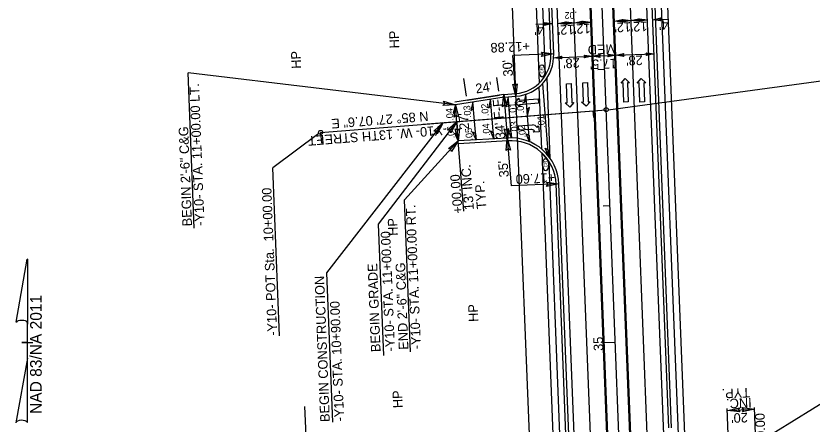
# Model space of a CAD drawing. Extents: x 1627861 to 1629601, y 761281 to 766239.
# Drawn here: x 1627974 to 1628556, y 763914 to 764213 of the extents above; entities that cross this region are included whole.
import ezdxf

# ---------------------------------------------------------------- set-up
doc = ezdxf.new("R2010")
doc.units = 0
for name, color, linetype in [('Cogo Default Point CELL', 7, 'Continuous'), ('Exist Hydro Jurisdictional Stream or Body of Water', 7, 'Continuous'), ('Exist Other Culture Sign Leader', 7, 'Continuous'), ('Exist Property Tie Line Leader', 7, 'Continuous'), ('Exist Property Tie Line Text', 7, 'Continuous'), ('Exist Right of Way Line Leader', 7, 'Continuous'), ('Exist Right of Way Monument Leader', 7, 'Continuous'), ('Exist Right of Way Monument Text', 7, 'Continuous'), ('Exist Utilities Gas Meter CELL', 7, 'Continuous'), ('Exist Utilities Gas Meter Cogo Elevation', 7, 'Continuous'), ('Exist Utilities Gas Meter Cogo Number', 7, 'Continuous'), ('Exist Utilities Gas UG Line', 7, 'Continuous'), ('Exist Utilities Power UG Cable SUE LOS B Cogo Number', 7, 'Continuous'), ('Exist Utilities Power UG Cable SUE LOS B Cogo Point CELL', 7, 'Continuous'), ('Exist Utilities Telephone UG Cable SUE LOS B Cogo Comment', 7, 'Continuous'), ('Exist Utilities Water Fire Hydrant Cogo Elevation', 7, 'Continuous'), ('Exist Utilities Water Fire Hydrant Cogo Number', 7, 'Continuous'), ('Exist Utilities Water Meter Cogo Elevation', 7, 'Continuous'), ('Exist Utilities Water UG Line SUE LOS B Cogo Number', 7, 'Continuous'), ('Exist Utilities Water Valve CELL', 7, 'Continuous'), ('Matchline', 7, 'Continuous'), ('Scratch_Level_0', 7, 'Continuous'), ('Typical Terminator CELL', 7, 'Continuous')]:
    doc.layers.add(name, color=color, linetype=linetype)

msp = doc.modelspace()

# ---------------------------------------------------------------- linework, layer by layer
at = {"layer": 'Exist Hydro Jurisdictional Stream or Body of Water'}
msp.add_line((1628196.62, 764127.74), (1628405.69, 764144.37), dxfattribs=at)
at = {"layer": 'Exist Property Tie Line Text'}
for p, q in [((1628404.53, 764173.83), (1628399.53, 764173.64)), ((1628395.99, 764143.6), (1628396.39, 764138.61)), ((1628296.31, 764135.67), (1628296.7, 764130.68)), ((1628408.47, 764073.91), (1628403.47, 764073.71))]:
    msp.add_line(p, q, dxfattribs=at)
at = {"layer": 'Exist Right of Way Line Leader'}
for p, q in [((1628407.18, 764144.24), (1628629.31, 764174.43)), ((1628195.42, 764126.85), (1628161.61, 764101.87)), ((1628166.47, 763978.73), (1628161.61, 764101.87)), ((1628190.01, 763805.52), (1628185.22, 763927.11))]:
    msp.add_line(p, q, dxfattribs=at)
for centre in [(1628405.69, 764144.37), (1628196.62, 764127.74)]:
    msp.add_circle(centre, 1.5, dxfattribs=at)
at = {"layer": 'Exist Right of Way Monument Leader'}
for p, q in [((1628416.62, 764163.87), (1628419.6, 764167.13)), ((1628419.6, 764167.13), (1628422.91, 764164.09)), ((1628428.42, 764163.86), (1628431.41, 764167.12)), ((1628431.41, 764167.12), (1628434.72, 764164.09)), ((1628376.73, 764163.38), (1628380.03, 764163.49)), ((1628377.23, 764149.39), (1628376.73, 764163.38)), ((1628380.03, 764163.49), (1628380.53, 764149.5)), ((1628388.71, 764164.04), (1628392, 764164.16)), ((1628389.21, 764150.05), (1628388.71, 764164.04)), ((1628392, 764164.16), (1628392.51, 764150.16)), ((1628418.12, 764163.92), (1628416.62, 764163.87)), ((1628418.62, 764149.93), (1628418.12, 764163.92)), ((1628422.91, 764164.09), (1628421.42, 764164.04)), ((1628421.42, 764164.04), (1628421.92, 764150.05)), ((1628429.92, 764163.91), (1628428.42, 764163.86)), ((1628430.42, 764149.92), (1628429.92, 764163.91)), ((1628434.72, 764164.09), (1628433.22, 764164.03)), ((1628433.22, 764164.03), (1628433.72, 764150.04)), ((1628338.98, 764149.31), (1628341.87, 764152.75)), ((1628342.37, 764146.46), (1628338.98, 764149.31)), ((1628341.87, 764152.75), (1628341.99, 764151.25)), ((1628341.99, 764151.25), (1628355.95, 764152.35)), ((1628356.2, 764149.06), (1628342.25, 764147.96)), ((1628342.25, 764147.96), (1628342.37, 764146.46)), ((1628355.95, 764152.35), (1628356.2, 764149.06)), ((1628375.73, 764149.33), (1628377.23, 764149.39)), ((1628379.04, 764146.3), (1628375.73, 764149.33)), ((1628382.03, 764149.56), (1628379.04, 764146.3)), ((1628380.53, 764149.5), (1628382.03, 764149.56)), ((1628387.71, 764149.99), (1628389.21, 764150.05)), ((1628391.02, 764146.96), (1628387.71, 764149.99)), ((1628394.01, 764150.22), (1628391.02, 764146.96)), ((1628392.51, 764150.16), (1628394.01, 764150.22)), ((1628421.92, 764150.05), (1628418.62, 764149.93)), ((1628433.72, 764150.04), (1628430.42, 764149.92)), ((1628341.2, 764132.57), (1628351.73, 764133.28)), ((1628341.43, 764129.28), (1628341.2, 764132.57)), ((1628350.56, 764129.9), (1628341.43, 764129.28)), ((1628355.31, 764131.42), (1628356.29, 764132.54)), ((1628356.29, 764132.54), (1628356.64, 764128.15)), ((1628352.15, 764127.8), (1628353.13, 764128.92)), ((1628356.64, 764128.15), (1628352.15, 764127.8))]:
    msp.add_line(p, q, dxfattribs=at)
for centre, radius, start, end in [((1628350.79, 764126.65), 3.28, 44.21033, 93.8685), ((1628351.29, 764128.07), 5.25, 39.88073, 85.19243)]:
    msp.add_arc(centre, radius, start, end, dxfattribs=at)
at = {"layer": 'Exist Right of Way Monument Text'}
for p, q in [((1628451.66, 763911.37), (1628428.17, 764506.9)), ((1628418.64, 763593.94), (1628385.15, 764443.28)), ((1628438.1, 763544.67), (1628404.6, 764394.05)), ((1628367.3, 764185.25), (1628364.7, 764251.23)), ((1628303.48, 764154.31), (1628301.49, 764167.26)), ((1628327.2, 764157.95), (1628325.67, 764167.94)), ((1628330.93, 764153.47), (1628295.33, 764147.99)), ((1628330.93, 764153.47), (1628339.7, 764154.17)), ((1628333.31, 764123.56), (1628297.44, 764121.45)), ((1628385.75, 763717.49), (1628371.05, 764090.05))]:
    msp.add_line(p, q, dxfattribs=at)
for centre, radius, start, end in [((1628337.32, 764184.07), 30, 274.54789, 2.25819), ((1628336.08, 764088.67), 35, 2.25819, 94.54789)]:
    msp.add_arc(centre, radius, start, end, dxfattribs=at)
at = {"layer": 'Exist Utilities Gas Meter CELL'}
for p, q in [((1628486.22, 762102.11), (1628373.12, 764970.45)), ((1628196.62, 764127.74), (1628405.69, 764144.37)), ((1628196.62, 764127.74), (1628405.69, 764144.37)), ((1628271.43, 764133.69), (1628405.69, 764144.37))]:
    msp.add_line(p, q, dxfattribs=at)
at = {"layer": 'Exist Utilities Gas Meter Cogo Elevation'}
for p, q in [((1628453.66, 763911.45), (1628430.17, 764506.97)), ((1628365.3, 764185.18), (1628362.7, 764251.15)), ((1628330.62, 764155.45), (1628295.02, 764149.97)), ((1628330.77, 764155.46), (1628339.54, 764156.16)), ((1628333.42, 764121.57), (1628297.56, 764119.45)), ((1628383.75, 763717.41), (1628369.06, 764089.97))]:
    msp.add_line(p, q, dxfattribs=at)
for centre, radius, start, end in [((1628337.32, 764184.07), 28, 274.54789, 2.25819), ((1628336.08, 764088.67), 33, 2.25819, 94.54789)]:
    msp.add_arc(centre, radius, start, end, dxfattribs=at)
at = {"layer": 'Exist Utilities Gas Meter Cogo Number'}
for points in [[(1628445.76, 764209.48), (1628439.87, 764210.25), (1628445.71, 764211.52), (1628445, 764210.46)], [(1628360.54, 764208.13), (1628366.43, 764207.36), (1628360.59, 764206.09), (1628361.3, 764207.16)], [(1628376.31, 764206.74), (1628370.42, 764207.52), (1628376.26, 764208.79), (1628375.56, 764207.72)], [(1628376.53, 764208.76), (1628382.41, 764207.99), (1628376.58, 764206.72), (1628377.28, 764207.79)], [(1628388.3, 764207.21), (1628382.41, 764207.99), (1628388.25, 764209.26), (1628387.55, 764208.19)], [(1628388.52, 764209.24), (1628394.41, 764208.46), (1628388.57, 764207.19), (1628389.27, 764208.26)], [(1628417.78, 764208.37), (1628411.89, 764209.15), (1628417.73, 764210.42), (1628417.02, 764209.35)], [(1628418, 764210.4), (1628423.88, 764209.62), (1628418.05, 764208.35), (1628418.75, 764209.42)], [(1628429.77, 764208.85), (1628423.88, 764209.62), (1628429.72, 764210.89), (1628429.01, 764209.83)], [(1628429.99, 764210.87), (1628435.87, 764210.1), (1628430.04, 764208.83), (1628430.74, 764209.89)], [(1628358.25, 764186.45), (1628367.3, 764185.25), (1628358.32, 764183.3), (1628359.41, 764184.94)], [(1628373.29, 764181.55), (1628367.41, 764182.38), (1628373.26, 764183.59), (1628372.55, 764182.53)], [(1628389.51, 764184.31), (1628395.39, 764183.48), (1628389.54, 764182.26), (1628390.26, 764183.33)], [(1628401.27, 764182.65), (1628395.39, 764183.48), (1628401.24, 764184.7), (1628400.52, 764183.64)], [(1628407, 764185), (1628412.88, 764184.17), (1628407.03, 764182.95), (1628407.74, 764184.01)], [(1628418.76, 764183.34), (1628412.88, 764184.17), (1628418.73, 764185.39), (1628418.01, 764184.32)], [(1628434.98, 764186.1), (1628440.86, 764185.27), (1628435.01, 764184.06), (1628435.72, 764185.12)], [(1628340.53, 764163.26), (1628339.7, 764154.17), (1628337.39, 764163.06), (1628339.08, 764162.04)], [(1628329.94, 764146.37), (1628330.77, 764155.46), (1628333.08, 764146.57), (1628331.39, 764147.59)], [(1628286.57, 764150.6), (1628295.33, 764147.99), (1628286.15, 764147.48), (1628287.48, 764148.93)], [(1628294.5, 764138.9), (1628295.33, 764147.99), (1628297.64, 764139.1), (1628295.95, 764140.12)], [(1628289.61, 764129.46), (1628296.31, 764135.67), (1628292.08, 764127.51), (1628291.51, 764129.39)], [(1628279.6, 764128.71), (1628286.34, 764134.87), (1628282.06, 764126.74), (1628281.5, 764128.63)], [(1628298.27, 764130.54), (1628297.44, 764121.45), (1628295.13, 764130.34), (1628296.81, 764129.32)], [(1628334.3, 764130.66), (1628333.46, 764121.57), (1628331.15, 764130.46), (1628332.84, 764129.44)], [(1628290.22, 764115.85), (1628297.44, 764121.45), (1628292.52, 764113.69), (1628292.11, 764115.61)], [(1628332.47, 764114.47), (1628333.31, 764123.56), (1628335.62, 764114.67), (1628333.93, 764115.69)], [(1628362, 764091.25), (1628371.05, 764090.05), (1628362.07, 764088.1), (1628363.16, 764089.74)], [(1628503.49, 763923.03), (1628494.43, 763924.22), (1628503.41, 763926.18), (1628502.33, 763924.53)], [(1628505.36, 763926.2), (1628514.42, 763925.01), (1628505.44, 763923.06), (1628506.52, 763924.7)]]:
    msp.add_lwpolyline(points, close=True, dxfattribs=at)
at = {"layer": 'Exist Utilities Gas UG Line'}
for p, q in [((1628462.18, 763238.38), (1628400.83, 764794.17)), ((1628474.17, 763238.85), (1628412.82, 764794.64)), ((1628408.48, 763242.45), (1628347.37, 764792.06)), ((1628420.44, 763243.74), (1628359.36, 764792.53))]:
    msp.add_line(p, q, dxfattribs=at)
at = {"layer": 'Exist Utilities Power UG Cable SUE LOS B Cogo Number'}
for p, q in [((1627973.72, 763988.67), (1627981.94, 764035.02)), ((1627981.99, 764035.02), (1627981.94, 764035.02)), ((1627981.99, 764035.02), (1627981.94, 764035.02)), ((1627981.99, 764035.02), (1627981.97, 763987.22)), ((1627981.96, 763962.42), (1627981.97, 763988.62)), ((1627981.97, 763987.22), (1627981.97, 763988.57)), ((1627977.96, 763974.02), (1627977.91, 763974.02)), ((1627981.51, 763974.02), (1627977.96, 763974.02)), ((1627978.01, 763974.02), (1627986.01, 763974.02)), ((1627981.96, 763962.42), (1627973.59, 763915.17)), ((1627981.99, 763915.37), (1627981.96, 763962.42))]:
    msp.add_line(p, q, dxfattribs=at)
for centre, start_param, end_param in [((1627977.86, 763988.17), 0.216388, 2.908219), ((1627977.82, 763915), 0.201328, 3.141593)]:
    msp.add_ellipse(centre, major_axis=(4.23, -0.03), ratio=0.461098, start_param=start_param, end_param=end_param, dxfattribs=at)
at = {"layer": 'Exist Utilities Telephone UG Cable SUE LOS B Cogo Comment'}
for p, q in [((1628364.82, 764108.66), (1628362.49, 764167.74)), ((1628358.54, 764115.52), (1628356.74, 764161.2))]:
    msp.add_line(p, q, dxfattribs=at)
at = {"layer": 'Exist Utilities Water Fire Hydrant Cogo Elevation'}
for centre in [(1628358.72, 764172.77), (1628361.35, 764104.08)]:
    msp.add_ellipse(centre, major_axis=(-0.18, 4.48), ratio=0.462467, dxfattribs=at)
at = {"layer": 'Exist Utilities Water Fire Hydrant Cogo Number'}
for p, q in [((1628341.38, 764111.82), (1628333.03, 764325.09)), ((1628358.23, 763687.61), (1628341.38, 764111.82))]:
    msp.add_line(p, q, dxfattribs=at)
at = {"layer": 'Exist Utilities Water Meter Cogo Elevation'}
for p, q in [((1628196.62, 764127.74), (1628197.26, 764119.76)), ((1628412.41, 763973.99), (1628404.42, 763973.67))]:
    msp.add_line(p, q, dxfattribs=at)
at = {"layer": 'Exist Utilities Water UG Line SUE LOS B Cogo Number'}
for p, q in [((1628363.52, 764110.4), (1628359.29, 764163.64)), ((1628336.38, 764123.67), (1628334, 764153.71)), ((1628349.64, 764120.94), (1628346.88, 764155.64)), ((1628297.44, 764121.45), (1628295.33, 764147.99)), ((1628310.42, 764122.21), (1628308.21, 764149.98)), ((1628323.4, 764122.98), (1628321.09, 764151.96))]:
    msp.add_line(p, q, dxfattribs=at)
at = {"layer": 'Exist Utilities Water Valve CELL'}
for p, q in [((1628463.98, 763890.82), (1628438.75, 764530.5)), ((1628434.01, 764523.77), (1628458.75, 763896.41)), ((1628352.29, 764273.92), (1628356.64, 764163.8)), ((1628361.4, 764169.79), (1628357.55, 764267.59)), ((1628358.65, 764112.75), (1628375.17, 763693.88)), ((1628363.9, 764106.42), (1628358.65, 764112.75)), ((1628379.91, 763700.61), (1628363.9, 764106.42))]:
    msp.add_line(p, q, dxfattribs=at)
at = {"layer": 'Matchline'}
for p, q in [((1628419.39, 763593.97), (1628385.9, 764443.31)), ((1628437.35, 763544.64), (1628403.85, 764393.98))]:
    msp.add_line(p, q, dxfattribs=at)
at = {"layer": 'Scratch_Level_0'}
for p, q in [((1628354.12, 764206.87), (1628366.43, 764207.36)), ((1628370.42, 764207.52), (1628382.41, 764207.99)), ((1628382.41, 764207.99), (1628394.41, 764208.46)), ((1628411.89, 764209.15), (1628423.88, 764209.62)), ((1628423.88, 764209.62), (1628435.87, 764210.1)), ((1628439.87, 764210.25), (1628451.18, 764210.7)), ((1628367.3, 764185.25), (1628337.32, 764184.07)), ((1628339.7, 764154.17), (1628337.32, 764184.07)), ((1628367.41, 764182.38), (1628395.39, 764183.48)), ((1628395.39, 764183.48), (1628412.88, 764184.17)), ((1628412.88, 764184.17), (1628440.86, 764185.27)), ((1628104.06, 764057.63), (1628099.58, 764171.36)), ((1628295.33, 764147.99), (1628099.58, 764171.36)), ((1628303.94, 764151.34), (1628327.66, 764154.99)), ((1628330.77, 764155.46), (1628333.46, 764121.57)), ((1628297.44, 764121.45), (1628295.33, 764147.99)), ((1628296.31, 764135.67), (1628238.81, 764060.52)), ((1628286.34, 764134.87), (1628201.02, 764024.79)), ((1628297.44, 764121.45), (1628257.98, 764078.27)), ((1628301.52, 764070.1), (1628297.44, 764121.45)), ((1628333.31, 764123.56), (1628336.08, 764088.67)), ((1628371.05, 764090.05), (1628336.08, 764088.67)), ((1628262.37, 763966.96), (1628257.98, 764078.27)), ((1628238.81, 764060.52), (1628242.6, 763964.28)), ((1628201.02, 764024.79), (1628205.33, 763915.62)), ((1628487.81, 763882.77), (1628675.94, 763999.17)), ((1628516, 763884.77), (1628514.37, 763926.29)), ((1628496, 763884.5), (1628494.38, 763925.48)), ((1628494.43, 763924.22), (1628514.42, 763925.01))]:
    msp.add_line(p, q, dxfattribs=at)
at = {"layer": 'Typical Terminator CELL'}
for points in [[(1628334, 764153.71), (1628332.48, 764147.57), (1628334.36, 764149.1)], [(1628346.88, 764155.64), (1628345.37, 764149.5), (1628347.25, 764151.03)], [(1628295.33, 764147.99), (1628293.81, 764141.85), (1628295.69, 764143.38)], [(1628308.21, 764149.98), (1628306.69, 764143.84), (1628308.58, 764145.37)], [(1628321.09, 764151.96), (1628319.58, 764145.82), (1628321.46, 764147.35)], [(1628348.14, 764139.79), (1628349.66, 764145.93), (1628347.78, 764144.4)], [(1628297.44, 764121.45), (1628294.97, 764127.27), (1628297.07, 764126.06)], [(1628310.42, 764122.21), (1628307.95, 764128.03), (1628310.05, 764126.82)], [(1628323.4, 764122.98), (1628320.93, 764128.8), (1628323.03, 764127.59)], [(1628336.38, 764123.67), (1628333.92, 764129.49), (1628336.02, 764128.28)], [(1628349.64, 764120.94), (1628347.17, 764126.76), (1628349.28, 764125.55)], [(1628363.52, 764110.4), (1628361.05, 764116.22), (1628363.16, 764115.01)]]:
    msp.add_lwpolyline(points, close=True, dxfattribs=at)

# ---------------------------------------------------------------- texts
at = {"layer": 'Cogo Default Point CELL'}
msp.add_text('N 85%%d 27\' 07.6" E', height=7, rotation=184.54789, dxfattribs=at).set_placement((1628275.31, 764143.13))
at = {"layer": 'Exist Other Culture Sign Leader'}
for s, rotation, p in [('HP', 92.25819, (1628254.31, 764189.38)), ('HP', 92.25819, (1628182.44, 764174.48)), ('-Y10- W. 13TH STREET', 184.54789, (1628288.87, 764133)), ('HP', 92.25819, (1628253.23, 764052.12)), ('-Y10- STA. 11+00.00', 92.25819, (1628251.08, 763967.42)), ('BEGIN GRADE', 92.25819, (1628240.59, 763967.01)), ('BEGIN CONSTRUCTION', 92.25819, (1628203.42, 763915.81)), ('-Y10- STA. 10+90.00', 92.25819, (1628213.91, 763916.23)), ('HP', 92.25819, (1628312.16, 763989.12)), ('HP', 92.25819, (1628256.82, 763925.97))]:
    msp.add_text(s, height=7, rotation=rotation, dxfattribs=at).set_placement(p)
at = {"layer": 'Exist Property Tie Line Leader'}
msp.add_text('35', height=7, rotation=92.25819, dxfattribs=at).set_placement((1628403.64, 763967.88))
at = {"layer": 'Exist Right of Way Line Leader'}
msp.add_text('-Y10- POT Sta.  10+00.00', height=7, rotation=92.25819, dxfattribs=at).set_placement((1628164.87, 763978.97))
at = {"layer": 'Exist Utilities Power UG Cable SUE LOS B Cogo Number'}
msp.add_text('NAD 83/NA 2011', height=8.5, rotation=89.97566, dxfattribs=at).set_placement((1627992.46, 763921.59))
at = {"layer": 'Exist Utilities Power UG Cable SUE LOS B Cogo Point CELL'}
for s, rotation, p in [("4'", 182.78623, (1628359.73, 764206.42)), ("12'", 182.78623, (1628382.29, 764206.62)), ("12'", 182.78623, (1628394.14, 764207.37)), ("12'", 182.78623, (1628423.78, 764208.51)), ("12'", 182.78623, (1628435.71, 764208.98)), ("4'", 182.78623, (1628451.13, 764210.03)), ('+12.88', 182.25819, (1628349.76, 764194.28)), ('MED', 182.25819, (1628412.9, 764192.43)), ("28'", 182.25819, (1628386.23, 764182.13)), ("28'", 182.25819, (1628432.35, 764184.1)), ("30'", 94.54789, (1628337.54, 764168.96)), ("17.5'", 182.25819, (1628413.5, 764181.72)), ("24'", 8.86252, (1628310.6, 764156.2)), ('-Y10- STA. 11+00.00 LT.', 92.25819, (1628111.7, 764059.45)), ("34' F-F", 94.54789, (1628331.92, 764123.09)), ("27'", 94.54789, (1628305.46, 764130.02)), ('BEGIN 2\'-6" C&G', 92.25819, (1628102.53, 764059.09)), ("35'", 94.54789, (1628334.47, 764095.14)), ("13' INC.", 94.54789, (1628308.95, 764071.11)), ('+00.00', 94.54789, (1628300.71, 764068.5)), ('+17.60', 182.25819, (1628368.21, 764098.06)), ('TYP.', 94.54789, (1628318.09, 764071.84)), ('-Y10- STA. 11+00.00 RT.', 92.25819, (1628270.12, 763969.1)), ('END 2\'-6" C&G', 92.25819, (1628260.95, 763968.74)), ('TYP.', 182.25895, (1628510.9, 763940.72)), ('INC.', 182.25895, (1628512.12, 763933.33)), ("20'", 182.25895, (1628509.3, 763922.47)), ('+00.00', 92.05859, (1628522.72, 763893.46))]:
    msp.add_text(s, height=7, rotation=rotation, dxfattribs=at).set_placement(p)
at = {"layer": 'Exist Utilities Water Fire Hydrant Cogo Elevation'}
for p in [(1628359.98, 764170.93), (1628362.61, 764102.25)]:
    msp.add_text('CR', height=2.4, rotation=92.25819, dxfattribs=at).set_placement(p)
at = {"layer": 'Exist Utilities Water UG Line SUE LOS B Cogo Number'}
for s, rotation, p in [('.02', 182.25819, (1628384.42, 764216.09)), ('.03', 94.54789, (1628306.85, 764138.39)), ('.02', 94.54789, (1628319.77, 764139.76)), ('.01', 94.54789, (1628340.13, 764140.46)), ('.00', 94.54789, (1628345.72, 764141.89)), ('.04', 94.54789, (1628293.97, 764136.44)), ('.03', 94.54789, (1628341.24, 764126.8)), ('.01', 94.54789, (1628361, 764131.26)), ('.06', 94.54789, (1628294.8, 764123.45)), ('.05', 94.54789, (1628308.11, 764121.95)), ('.04', 94.54789, (1628320.74, 764125.21)), ('.02', 94.54789, (1628346.96, 764124.15))]:
    msp.add_text(s, height=5, rotation=rotation, dxfattribs=at).set_placement(p)

doc.saveas('drawing.dxf')
